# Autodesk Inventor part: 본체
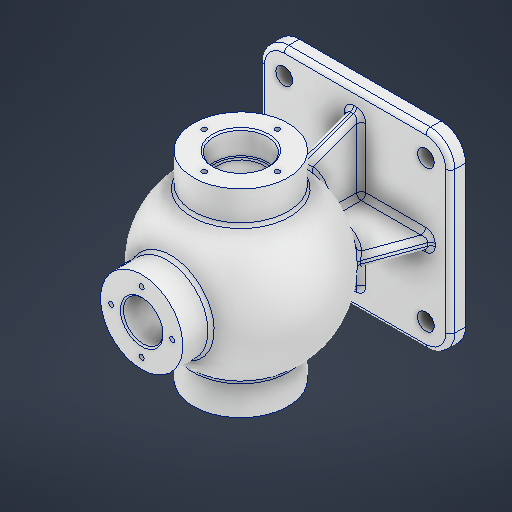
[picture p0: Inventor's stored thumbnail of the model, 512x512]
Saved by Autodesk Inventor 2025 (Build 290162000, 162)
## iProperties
Created: 2025-08
Part Number: 본체
Material: 알루미늄 6061
Document SubType Name: Modeling
Designer: infra006
Density: 2.7 g/cm^3
Appearance: 알루미늄 - 평지
Mass: 1536.91 g
Surface Area: 1167.84 cm^2
Volume: 569.226 cm^3
Author: infra006
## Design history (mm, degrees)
sketch "스케치1"
  geometry: L1 (-46.5, 62.5)-(46.5, 62.5); L2 (62.5, 46.5)-(62.5, -46.5); L3 (46.5, -62.5)-(-46.5, -62.5); L4 (-62.5, -46.5)-(-62.5, 46.5); L5 (-62.5, 62.5)-(62.5, -62.5); L6 (62.5, 62.5)-(-62.5, -62.5); A1 r 16 centre (-46.5, 46.5) between (-46.5, 62.5) and (-62.5, 46.5); A2 r 16 centre (-46.5, -46.5) between (-62.5, -46.5) and (-46.5, -62.5); A3 r 16 centre (46.5, -46.5) between (46.5, -62.5) and (62.5, -46.5); A4 r 16 centre (46.5, 46.5) between (62.5, 46.5) and (46.5, 62.5); 1 further point
  constraints: 12 end point, 8 point on circle, 8 point on line, 8 tangent, 4 centre point, 3 equal radius, 2 midpoint, 2 parallel, 1 horizontal, 1 perpendicular
  dimensions: "d0" = 125 distance of L5.end L6.end; "d1" = 125 distance of L6.start L5.end; "d2" = 16 radius of A1
extrude "돌출1" new body sketch "스케치1" distance "d3" = 10; taper "d4" = 0 deg
node "작업 평면1"
sketch "스케치2"
  geometry: L1 (-54, 0)-(54, 0); L2 (62.5, -46.5)-(62.5, 46.5) reference; L3 (46.5, 62.5)-(-46.5, 62.5) reference; A1 r 54 centre (0, 0) between (-54, 0) and (54, 0); 1 further point
  constraints: 2 end point, 2 point on circle, 1 centre point, 1 coincident, 1 perpendicular
  dimensions: "d8" = 108 diameter of A1; "d9" = 62.5 distance between parallel lines of L3 L1
revolve "회전1" sketch "스케치2" stored, may be unused: angle "d10" = 90 deg
sketch "스케치3"
  geometry: L1 (46.5, 10)-(-46.5, 10) reference; L2 (-37.385, 46.034)-(-50.5, 10); L3 (37.385, 46.034)-(50.5, 10); L4 (62.5, 0)-(62.5, 10) reference; L5 (-62.5, 0)-(-62.5, 10) reference; L6 (37.385, 46.034)-(-37.385, 46.034); L7 (-50.5, 10)-(50.5, 10); L8 (-46.5, 10)-(-62.5, 10) reference; C1 r 54 at (0, 85) reference; A1 r 54 centre (0, 85) between (-37.385, 46.034) and (37.385, 46.034) reference; 5 further points
  constraints: 8 end point, 2 point on circle, 2 point on line, 1 collinear
  dimensions: "d11" = 12 distance from line of L4 L3.end; "d12" = 12 distance from line of L5 L2.end; "d13" = 20 deg angle of L4 L3; "d14" = 20 deg angle of L5 L2
extrude "돌출2" join sketch "스케치3" stored distance "d15" = 8; taper "d16" = 0 deg
sketch "스케치4"
  geometry: L1 (-46.5, 10)-(46.5, 10) reference; L2 (-46.5, 10)-(-62.5, 10) reference; L3 (-37.385, 46.034)-(-50.5, 10); L4 (-62.5, 0)-(-62.5, 10) reference; L5 (37.385, 46.034)-(50.5, 10); L6 (62.5, 0)-(62.5, 10) reference; C1 r 54 at (0, 85) reference; A1 r 54 centre (0, 85) between (-37.385, 46.034) and (37.385, 46.034) reference; 2 further points
  constraints: 4 end point, 2 point on circle, 2 point on line
  dimensions: "d17" = 12 distance from line of L4 L3.end; "d18" = 20 deg angle of L4 L3; "d19" = 12 distance from line of L6 L5.end; "d20" = 20 deg angle of L6 L5
feature "리브1" dims "d21" = 1, "d22" = 8, "d23" = 0, "d24" = 0, "d25" = 1, "d26" = 1
feature "리브2" dims "d27" = 1, "d28" = 8, "d29" = 0, "d30" = 0, "d31" = 1, "d32" = 1
node "작업 평면2"
sketch "스케치7"
  geometry: L1 (65, 116)-(-65, 116); L2 (-65, 116)-(-65, 54); L3 (-65, 54)-(65, 54); L4 (65, 54)-(65, 116); L5 (46.5, 0)-(-46.5, 0) reference; L6 (65, 85)-(-65, 85); L7 (65, 102.5)-(49, 102.5); L8 (49, 102.5)-(49, 100); L9 (49, 100)-(-49, 100); L10 (-49, 102.5)-(-65, 102.5); L11 (-49, 102.5)-(-49, 100); 2 further points
  constraints: 20 end point, 4 parallel, 3 midpoint, 2 horizontal, 2 perpendicular, 2 point on line, 2 vertical
  dimensions: "d38" = 130 distance of L3.end L2.end; "d39" = 62 distance of L2.end L1.end; "d40" = 54 distance between parallel lines of L5 L3; "d41" = 65 distance from line of point (0, 0) L2; "d42" = 17.5 distance between parallel lines of L6 L7; "d43" = 16 distance of L7.start L7.end; "d44" = 2.5 distance of L7.end L8.end; "d45" = 16 distance between parallel lines of L2 L11; "d46" = 17.5 distance between parallel lines of L6 L10
sketch "스케치8"
  geometry: L1 (65, 116)-(-65, 116) reference; L2 (-65, 116)-(-65, 54) reference; L3 (-49, 102.5)-(-65, 102.5) reference; L4 (-49, 102.5)-(-49, 100) reference; L5 (49, 100)-(-49, 100) reference; L6 (49, 102.5)-(49, 100) reference; L7 (65, 102.5)-(49, 102.5) reference; L8 (65, 54)-(65, 116) reference; L9 (65, 85)-(-65, 85) reference; 1 further point
revolve "회전3" stored, may be unused: angle "d47" = 90 deg
sketch "스케치9"
  geometry: L1 (27, 150)-(-27, 150); L2 (46.5, 0)-(-46.5, 0) reference; L3 (27, 150)-(27, 92.205); L4 (27, 92.205)-(-27, 92.205); L5 (-27, 92.205)-(-27, 150); L6 (13, 150)-(13, 92.205); L7 (-13, 150)-(-13, 92.205); L8 (0, 150)-(0, 92.205); 2 further points
  constraints: 14 end point, 4 point on line, 3 midpoint, 2 perpendicular, 2 vertical, 1 horizontal, 1 parallel
  dimensions: "d48" = 150 distance between parallel lines of L2 L1; "d49" = 54 distance of L1.start L1.end; "d50" = 27 horizontal distance of point (0, 0) L1.end; "d51" = 13 distance from line of L8.start L6; "d52" = 26 distance between parallel lines of L6 L7; "d60" = 57.7948 distance between parallel lines of L1 L4
revolve "회전4" stored, may be unused: angle "d53" = 90 deg
sketch "스케치10" dims "d54" = 88
  geometry: L1 (44, 0)-(-95.364, 0); 3 further points
  constraints: 2 end point, 1 coincident, 1 horizontal, 3 other
  dimensions: "d55" = 139.36443 distance of L1.start L1.end; "d56" = 0 distance from line of point (0, 0) L1
revolve "회전5" sketch "스케치10" stored, may be unused: angle "d57" = 90 deg
revolve "회전6" stored, may be unused: angle "d58" = 90 deg
revolve "회전7" stored, may be unused: angle "d59" = 90 deg
sketch "스케치11"
  geometry: L1 (-46.5, -85)-(46.5, -85) reference; L2 (62.5, -85)-(62.5, -75) reference; L3 (0, 24)-(0, -24); L4 (-24, 0)-(24, 0); A1 r 24 centre (0, 0) between (0, 24) and (0, -24); 5 further points
  constraints: 4 coincident, 4 end point, 4 point on circle, 1 centre point, 1 horizontal, 1 vertical
  dimensions: "d61" = 48 diameter of A1; "d62" = 85 distance from line of L1 A1.centre; "d63" = 62.5 distance from line of L2 A1.centre; "d64" = 48 distance of L3.start L3.end; "d65" = 48 distance of L4.start L4.end
hole "구멍1" sketch "스케치11" at (0, 24), (-24, 0), (0, -24), (24, 0) diameter "d66" = 3.242; stored, may be unused: countersink angle "d70" = 90 deg, drill point angle "d72" = 118 deg; dims "d67" = 12, "d68" = 4, "d69" = 2, "d71" = 15
sketch "스케치12"
  geometry: L1 (46.5, 85)-(-46.5, 85) reference; L2 (-62.5, 85)-(-62.5, 75) reference; L3 (0, -24)-(0, 24); L4 (24, 0)-(-24, 0); C1 r 1.621 at (0, 24) reference; C2 r 1.621 at (24, 0) reference; C3 r 1.621 at (0, -24) reference; A1 r 24 centre (0, 0) between (0, -24) and (-24, 0); 5 further points
  constraints: 4 coincident, 4 end point, 2 point on circle, 1 centre point, 1 horizontal, 1 vertical
  dimensions: "d73" = 48 diameter of A1; "d74" = 85 distance from line of L1 A1.centre; "d75" = 62.5 distance from line of L2 A1.centre
hole "구멍2" sketch "스케치12" at (0, -24), (24, 0), (0, 24), (-24, 0) diameter "d76" = 3.242; stored, may be unused: countersink angle "d80" = 90 deg, drill point angle "d82" = 118 deg; dims "d77" = 12, "d78" = 4, "d79" = 2, "d81" = 15
sketch "스케치13"
  geometry: L1 (0, -20)-(0, 20); L2 (-4, 0)-(-37.385, 0) reference; L3 (-20, 0)-(20, 0); A1 r 20 centre (0, 0) between (0, -20) and (0, 20); 5 further points
  constraints: 5 coincident, 4 end point, 4 point on circle, 2 point on line, 1 centre point, 1 perpendicular
  dimensions: "d83" = 40 diameter of A1; "d84" = 40 distance of L1.start L1.end
hole "구멍3" sketch "스케치13" at (0, -20), (20, 0), (0, 20), (-20, 0) diameter "d85" = 3.242; stored, may be unused: countersink angle "d89" = 90 deg, drill point angle "d91" = 118 deg; dims "d86" = 9, "d87" = 4, "d88" = 2, "d90" = 11
node "작업 평면3"
sketch "스케치14"
  geometry: L1 (-14.253, 146.239)-(14.253, 146.239); L2 (14.253, 146.239)-(14.253, 135.761); L3 (14.253, 135.761)-(-14.253, 135.761); L4 (-14.253, 135.761)-(-14.253, 146.239); L5 (-14.253, 141)-(14.253, 141); L6 (0, 146.239)-(0, 135.761); L7 (27, 150)-(-27, 150) reference; L8 (65, 116)-(65, 54) reference; 1 further point
  constraints: 4 end point, 4 midpoint, 2 other
  dimensions: "d93" = 9 distance between parallel lines of L5 L7; "d94" = 65 distance between parallel lines of L8 L6
feature "엠보싱1" sketch "스케치14" dims "d95" = 0.5, "d96" = 0
chamfer "모따기1" distance "d97" = 1; stored, may be unused: second distance "d98" = 2, angle "d99" = 45 deg
chamfer "모따기2" distance "d100" = 1; stored, may be unused: second distance "d101" = 2, angle "d102" = 45 deg
fillet "모깎기1" dims "d103" = 0.6
chamfer "모따기3" distance "d104" = 1; stored, may be unused: second distance "d105" = 2, angle "d106" = 45 deg
feature "면 삭제1"
feature "면 삭제2"
fillet "모깎기2" dims "d107" = 3
fillet "모깎기3" dims "d108" = 3
feature "면 삭제3"
feature "면 삭제4"
fillet "모깎기4" dims "d109" = 3
fillet "모깎기5" dims "d110" = 3
fillet "모깎기6" dims "d111" = 3
sketch "스케치15"
  geometry: L1 (46.5, 46.5)-(-46.5, 46.5); L2 (-46.5, 46.5)-(-46.5, -46.5); L3 (-46.5, -46.5)-(46.5, -46.5); L4 (46.5, -46.5)-(46.5, 46.5); L5 (46.5, 46.5)-(-46.5, -46.5); L6 (-46.5, 46.5)-(46.5, -46.5); A1 r 13 centre (46.5, 46.5) between (59.5, 46.5) and (46.5, 59.5) reference; 5 further points
  constraints: 12 end point, 4 coincident, 2 midpoint, 2 parallel, 1 horizontal, 1 perpendicular
  dimensions: "d112" = 93 distance of L3.end L2.end; "d113" = 93 distance of L2.end L1.end
hole "구멍4" sketch "스케치15" at (46.5, 46.5), (-46.5, 46.5), (-46.5, -46.5), (46.5, -46.5) diameter "d114" = 11; stored, may be unused: countersink angle "d118" = 90 deg, drill point angle "d120" = 118 deg; dims "d115" = 9, "d116" = 4, "d117" = 2, "d119" = 11
feature "Ӿ耀Ԁ耀Ԃ耀Ԅ耀Ԇ耀Ԉ耀Ԋ耀Ԍ耀" dims "d0" = 125, "d1" = 125, "d2" = 16, "d3" = 10, "d4" = 0, "d5" = 85, "d8" = 108, "d9" = 62.5, "d10" = 90 deg, "d11" = 12, "d12" = 12, "d13" = 20 deg, "d14" = 20 deg, "d15" = 8, "d16" = 0, "d17" = 12, "d18" = 20 deg, "d19" = 12, "d20" = 20 deg, "d21" = 1, "d22" = 8, "d23" = 0, "d24" = 0, "d25" = 1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
node "솔리드1"
feature "A9D066F2-1C7D-4E18-AEED-F7BC21143FA4" dims "d114" = 11, "d115" = 9, "d116" = 4, "d117" = 2, "d118" = 90 deg, "d119" = 11, "d120" = 118 deg
